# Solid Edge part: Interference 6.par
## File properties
Last saved by: Lee
Revision: 59
Accuracy: 0.990
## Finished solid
Body 1: solid body, 4 faces, 4 edges, 0 vertices.
  Faces by surface: cylinder 4
  Edges by curve: intersection 4
Bounding box of the edges (mm): 101.889 x 219.073 x 304.967, from (-809.4284, 166.463, 214.5108) to (-707.5393, 385.5361, 519.4775).
Cylindrical faces by radius (mm): R91 x1, R109.5375 x1, R850 x1, R875.4 x1
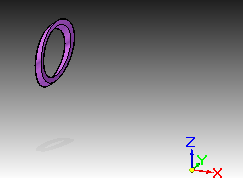
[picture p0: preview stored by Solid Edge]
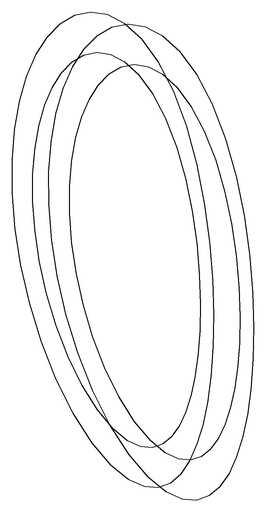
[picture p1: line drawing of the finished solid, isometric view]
